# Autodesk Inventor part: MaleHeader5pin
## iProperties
Shininess: 64.0
Length Units: 11272
Angle Units: 11279
Time Units: 11290
Mass Units: 11286
Length Display Precision: 3
Angle Display Precision: 2
Compacted: True
Part Number: MaleHeader5pin
Document SubType Name: Modeling
Created: 2006-08
Designer: jpalmisano
Manufacturer: Standard
Standards Organization: Custom
Density: 0.0
Volumn: 0.0
Area: 0.0
PropertySet Name: Model Information
Control State: 0
Master: False
Checked Out: False
Author: jpalmisano
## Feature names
1. Extrusion1
2. Extrusion2
